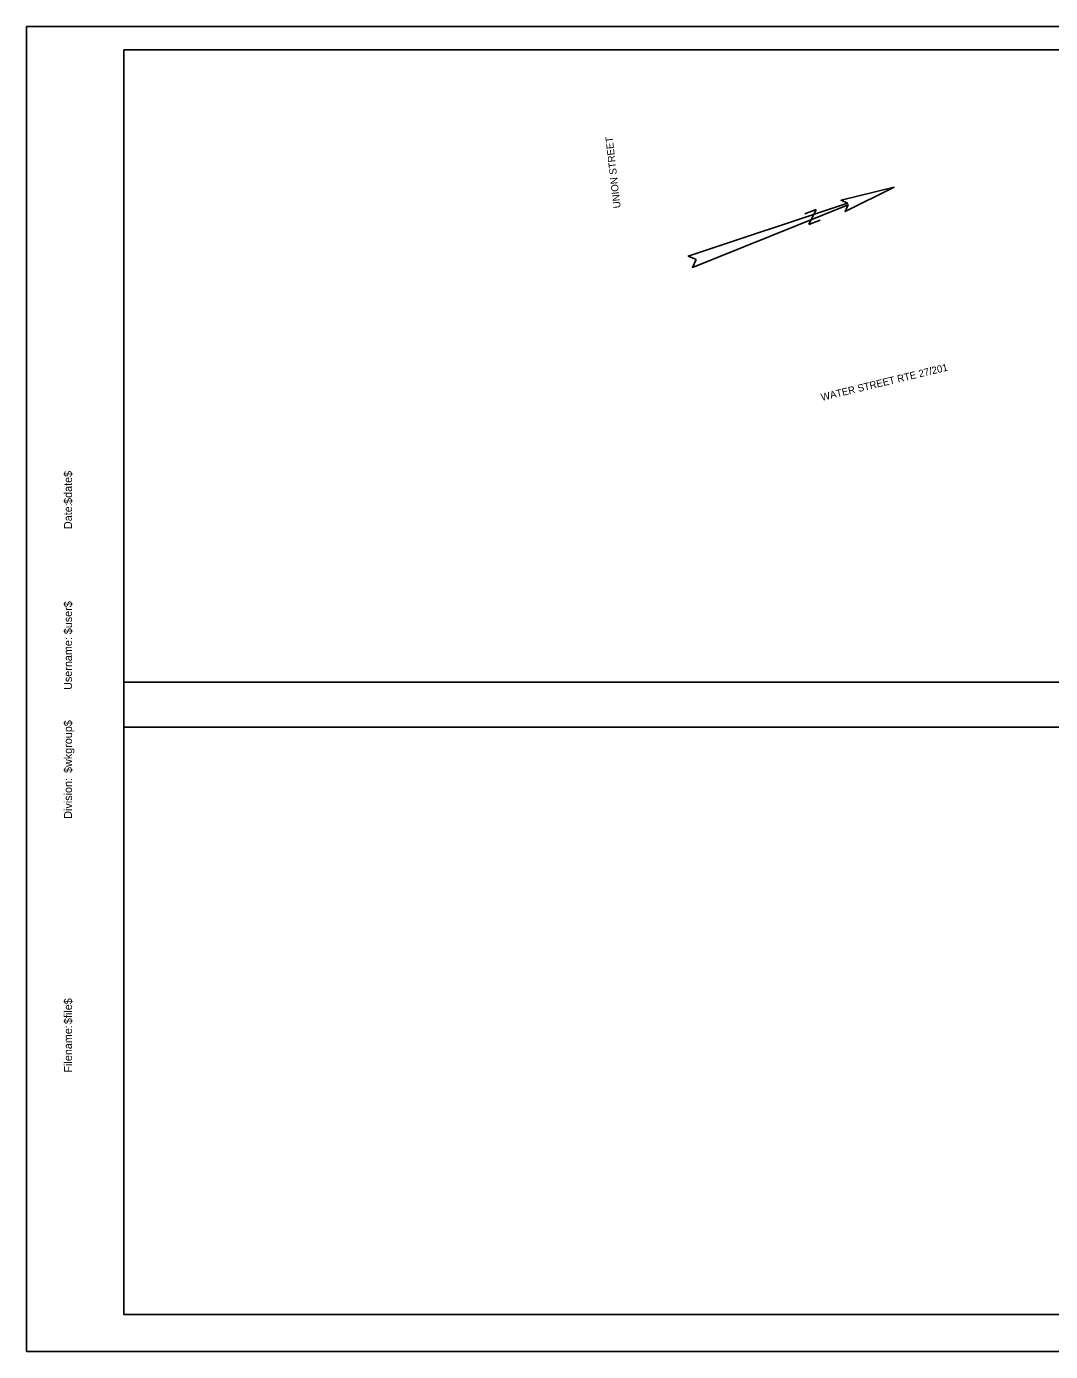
# Model space of a CAD drawing. Extents: x 0 to 850, y 0 to 550.
# Drawn here: x 0 to 425, y 0 to 550 of the extents above; entities that cross this region are included whole.
import ezdxf

# ---------------------------------------------------------------- set-up
doc = ezdxf.new("R2010")
doc.units = 0
for name, color, linetype in [('BORDER', 7, 'Continuous'), ('D_Roadway_Centerline_Text', 7, 'Continuous'), ('Default', 7, 'Continuous'), ('H_V CONTROLS', 7, 'Continuous'), ('PLOT BOUNDARY', 7, 'Continuous')]:
    doc.layers.add(name, color=color, linetype=linetype)

msp = doc.modelspace()

# ---------------------------------------------------------------- linework, layer by layer
at = {"layer": 'BORDER'}
for p, q in [((840.33, 540.24), (40.33, 540.24)), ((40.33, 540.24), (40.33, 15.24)), ((40.33, 15.24), (840.33, 15.24))]:
    msp.add_line(p, q, dxfattribs=at)
at = {"layer": 'Default'}
for points in [[(40.33, 15.24), (790.33, 15.24), (790.33, 540.26), (40.33, 540.26)], [(40.33, 540.24), (440.33, 540.24), (440.33, 277.76), (40.33, 277.76)], [(604.44, 259.17), (40.33, 259.17), (40.33, 15.24), (604.44, 15.24)]]:
    msp.add_lwpolyline(points, close=True, dxfattribs=at)
at = {"layer": 'H_V CONTROLS'}
for p, q in [((359.93, 483.23), (337.94, 477.85)), ((359.93, 483.23), (339.66, 473.15)), ((340.65, 476.59), (274.55, 454.66)), ((340.92, 475.86), (276.27, 449.96)), ((340.65, 476.59), (337.94, 477.85)), ((340.92, 475.86), (339.66, 473.15)), ((277.76, 453.17), (274.55, 454.66)), ((277.76, 453.17), (276.27, 449.96))]:
    msp.add_line(p, q, dxfattribs=at)
for points in [[(277.76, 453.17), (276.27, 449.96), (340.92, 475.86), (339.66, 473.15), (359.93, 483.23), (337.94, 477.85), (340.65, 476.59), (274.55, 454.66), (277.76, 453.17)], [(322.96, 472.22), (327.66, 473.94)], [(327.66, 473.94), (324.59, 467.78)], [(324.59, 467.78), (329.28, 469.5)]]:
    msp.add_lwpolyline(points, dxfattribs=at)
at = {"layer": 'PLOT BOUNDARY'}
msp.add_lwpolyline([(-0.13, -0.05), (849.87, -0.05), (849.87, 549.95), (-0.13, 549.95)], close=True, dxfattribs=at)

# ---------------------------------------------------------------- texts
at = {"layer": 'BORDER'}
for s, p in [('$date$', (18.76, 351.77)), ('Date:', (18.76, 341.33)), ('$user$', (18.76, 297.7)), ('Username:', (18.76, 274.58)), ('$wkgroup$', (18.76, 240.09)), ('Division:', (18.76, 221.08)), ('$file$', (18.76, 135.87)), ('Filename:', (18.76, 115.74))]:
    msp.add_text(s, height=3.348, rotation=90, dxfattribs=at).set_placement(p)
at = {"layer": 'D_Roadway_Centerline_Text'}
for s, rotation, p in [('UNION STREET', 96.488, (246.48, 474.68)), ('WATER STREET RTE 27/201', 13.5149, (330, 394.54))]:
    msp.add_text(s, height=3, rotation=rotation, dxfattribs=at).set_placement(p)

doc.saveas('drawing.dxf')
